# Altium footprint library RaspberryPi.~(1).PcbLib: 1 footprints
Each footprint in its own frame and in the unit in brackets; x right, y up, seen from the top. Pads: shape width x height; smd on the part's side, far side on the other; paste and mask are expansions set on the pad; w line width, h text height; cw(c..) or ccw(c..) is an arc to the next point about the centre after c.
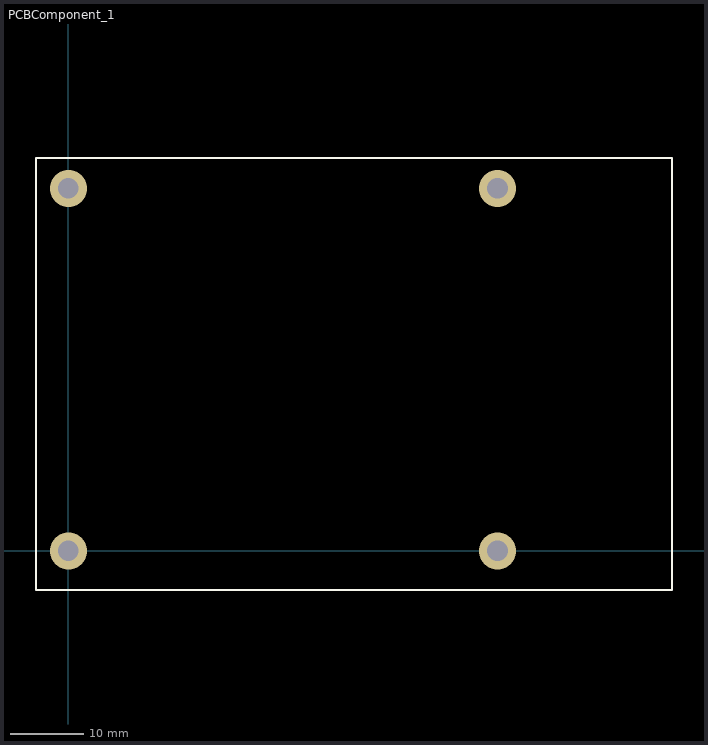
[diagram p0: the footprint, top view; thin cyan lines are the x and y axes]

## PCBComponent_1 [mm]
via 58,49 diameter 5 hole 2.8
via 0,49 diameter 5 hole 2.8
via 58,0 diameter 5 hole 2.8
via 0,0 diameter 5 hole 2.8
via -11.938,-90.932 diameter 3 hole 3
Top Overlay:
  lines w0.254: -4.4,-5.3 -4.4,53.1 81.6,53.1 81.6,-5.3 -4.4,-5.3
3D body: height 15, standoff 0, extent 46.5,27.8 57,41.1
